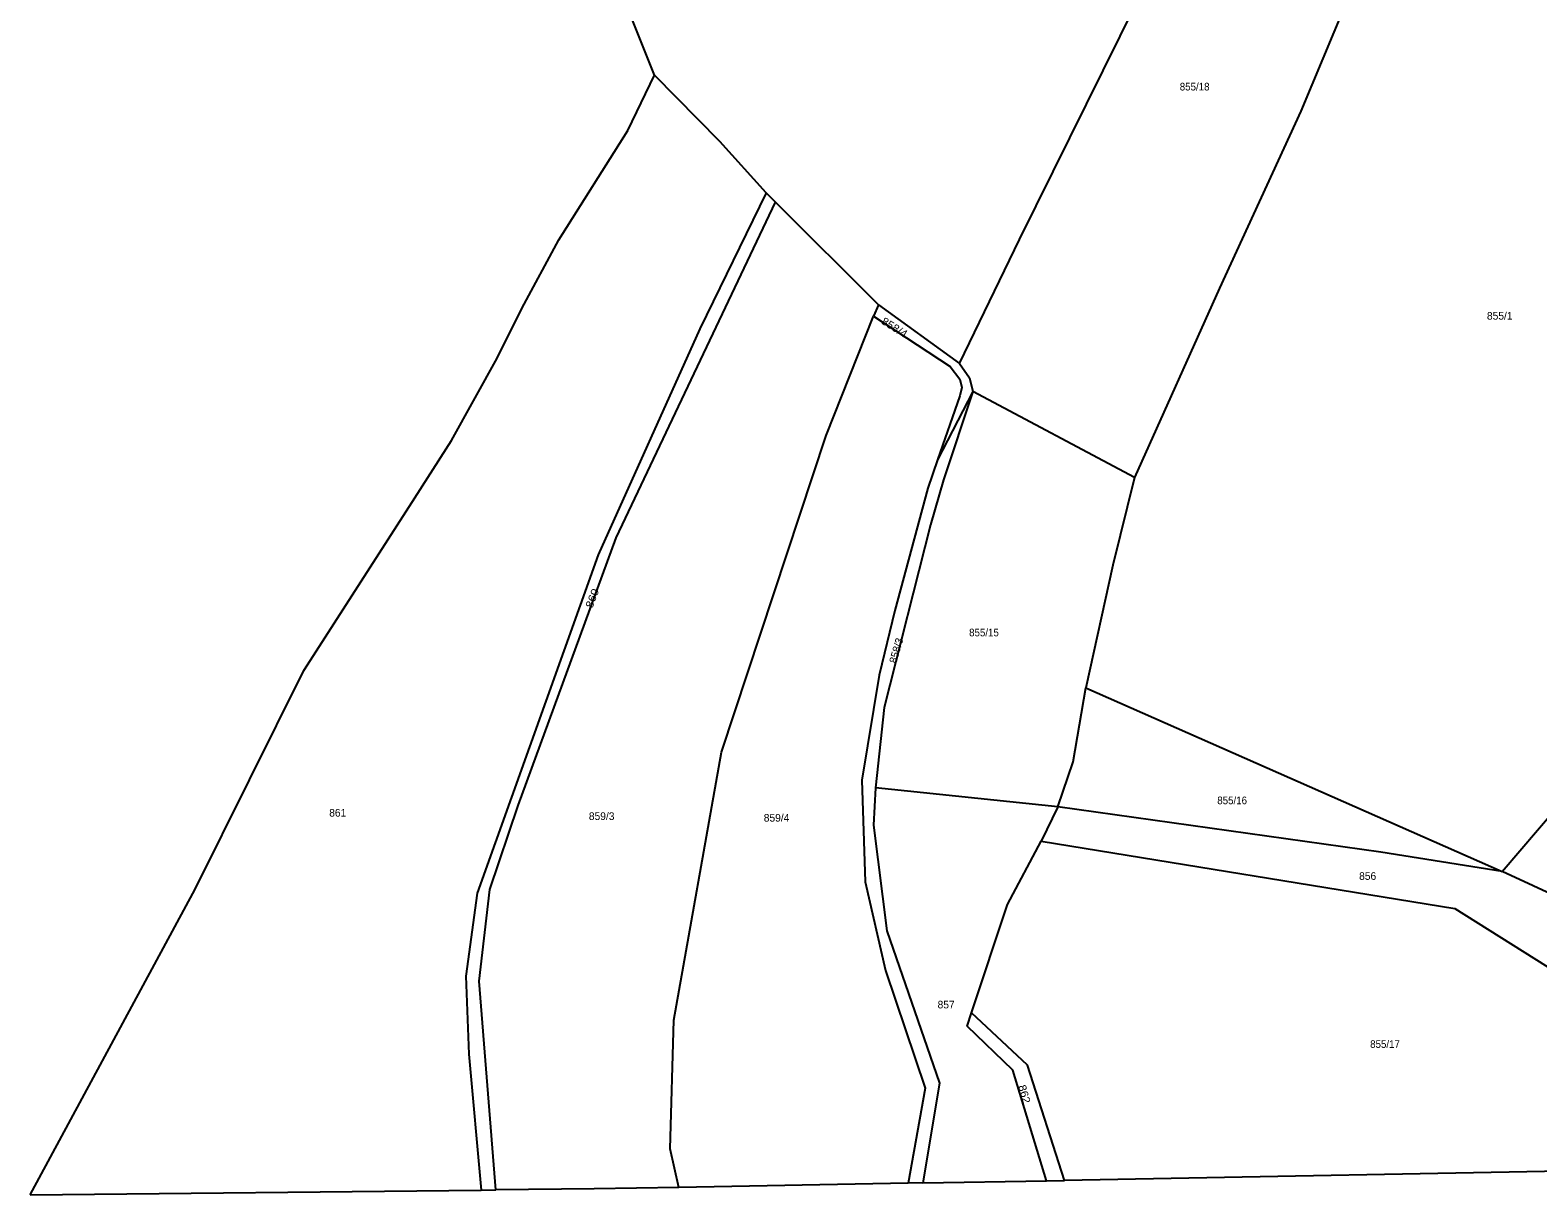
# Model space of a CAD drawing. Extents: x -687135 to -684370, y -1007309 to -1005782.
# Drawn here: x -686161.7 to -685826.9, y -1007308.8 to -1007050.2 of the extents above; entities that cross this region are included whole.
import ezdxf

# ---------------------------------------------------------------- set-up
doc = ezdxf.new("R2010")
doc.units = 0
doc.header["$LTSCALE"] = 0.68
doc.layers.add('1', color=7, linetype='Continuous', lineweight=25)
doc.layers.add('2', color=7, linetype='Continuous')

msp = doc.modelspace()

# ---------------------------------------------------------------- linework, layer by layer
at = {"layer": '1'}
for p, q in [((-685996.12, -1007088.35), (-685973.31, -1007111.15)), ((-685973.31, -1007111.15), (-685974.36, -1007113.66)), ((-685973.31, -1007111.15), (-685955.32, -1007124.17)), ((-685952.34, -1007130.44), (-685960.15, -1007145.6)), ((-685916.46, -1007149.49), (-685952.34, -1007130.44)), ((-685933.44, -1007222.64), (-685973.98, -1007218.44)), ((-685933.44, -1007222.64), (-685937.16, -1007230.29)), ((-685963.46, -1007306.2), (-685935.98, -1007305.71)), ((-685935.98, -1007305.71), (-685931.97, -1007305.63)), ((-686161.67, -1007308.85), (-686061.49, -1007307.79)), ((-686061.49, -1007307.79), (-686058.24, -1007307.76)), ((-685966.67, -1007306.26), (-686017.65, -1007307.19)), ((-685963.46, -1007306.2), (-685966.67, -1007306.26))]:
    msp.add_line(p, q, dxfattribs=at)
for points in [[(-685955.32, -1007124.17), (-685941.96, -1007096.65), (-685915.9, -1007044), (-685895.22, -1006995.76), (-685878.25, -1006963.02)], [(-685846.06, -1006988.01), (-685879.53, -1007068.15), (-685897.56, -1007107.5), (-685916.46, -1007149.49)], [(-686024.97, -1007055.32), (-686029.1, -1007045), (-686042.48, -1007024.33), (-686039.71, -1007008.65)], [(-686028.91, -1007072.46), (-686023.04, -1007060.16), (-686024.97, -1007055.32)], [(-685998.2, -1007086.28), (-686008.55, -1007074.89), (-686023.04, -1007060.16)], [(-686057.97, -1007123.03), (-686052.45, -1007112), (-686044.28, -1007096.71), (-686028.91, -1007072.46)], [(-685998.2, -1007086.28), (-686012.97, -1007116.48), (-686035.54, -1007166.68), (-686062.38, -1007241.82), (-686064.89, -1007260.27), (-686064.24, -1007277.61), (-686061.49, -1007307.79)], [(-686058.24, -1007307.76), (-686061.99, -1007261.37), (-686059.57, -1007241.06), (-686053.3, -1007222.35), (-686031.52, -1007162.93), (-685996.12, -1007088.35), (-685998.2, -1007086.28)], [(-686017.65, -1007307.19), (-686019.52, -1007298.6), (-686018.76, -1007270.05), (-686008.12, -1007210.56), (-685984.9, -1007140.21), (-685974.36, -1007113.66)], [(-685974.36, -1007113.66), (-685957.39, -1007124.85), (-685955.21, -1007127.66), (-685954.74, -1007129.52), (-685955.21, -1007131.39), (-685960.15, -1007145.6)], [(-686077.45, -1007155.91), (-686068.09, -1007141.32), (-686057.97, -1007123.03)], [(-685955.32, -1007124.17), (-685953.1, -1007127.35), (-685952.34, -1007130.44)], [(-685952.34, -1007130.44), (-685958.83, -1007150.06), (-685961.71, -1007160.02), (-685972.02, -1007200.58), (-685973.98, -1007218.44)], [(-685960.15, -1007145.6), (-685962.33, -1007151.87), (-685969.69, -1007179.06), (-685973.11, -1007193.39), (-685977.01, -1007216.74), (-685976.24, -1007239.3), (-685971.71, -1007259.05), (-685962.91, -1007285.14), (-685966.67, -1007306.26)], [(-685916.46, -1007149.49), (-685921.28, -1007169.02), (-685927.24, -1007196.24), (-685834.78, -1007237.06)], [(-686161.67, -1007308.85), (-686125.03, -1007240.98), (-686100.89, -1007192.42), (-686077.45, -1007155.91)], [(-685933.44, -1007222.64), (-685930.03, -1007212.67), (-685927.24, -1007196.24)], [(-685973.98, -1007218.44), (-685974.36, -1007226.74), (-685971.4, -1007250.22), (-685959.73, -1007284.01), (-685963.46, -1007306.2)], [(-685834.78, -1007237.06), (-685823.03, -1007223.25), (-685820.34, -1007219.84)], [(-685834.78, -1007237.06), (-685861.75, -1007232.73), (-685933.44, -1007222.64)], [(-685952.66, -1007268.42), (-685944.64, -1007244.37), (-685937.16, -1007230.29)], [(-685937.16, -1007230.29), (-685845.31, -1007245.22), (-685817.39, -1007262.76), (-685794.79, -1007289.87), (-685803.04, -1007266.06), (-685800.57, -1007257.03), (-685815.07, -1007246.11), (-685834.78, -1007237.06)], [(-685935.98, -1007305.71), (-685943.45, -1007281.18), (-685953.61, -1007271.35), (-685952.66, -1007268.42)], [(-685931.97, -1007305.63), (-685940.2, -1007280.06), (-685952.66, -1007268.42)], [(-685716.84, -1007305.32), (-685721.26, -1007305.36), (-685729.55, -1007305.43), (-685805.63, -1007303.31), (-685931.97, -1007305.63)], [(-686017.65, -1007307.19), (-686036.45, -1007307.53), (-686058.24, -1007307.76)]]:
    msp.add_lwpolyline(points, dxfattribs=at)

# ---------------------------------------------------------------- texts
at = {"layer": '2', "width": 0.95}
for s, p in [('855/18', (-685906.38, -1007063.559)), ('855/15', (-685953.16, -1007184.799)), ('855/16', (-685898.05, -1007222.09)), ('855/17', (-685864.1, -1007276.21))]:
    msp.add_text(s, height=1.7, dxfattribs=at).set_placement(p)
at = {"layer": '2'}
for s, rotation, width, p in [('858/4', 328, 1.1, (-685972.83, -1007115.25)), ('860', 69, 1.15, (-686036.836, -1007178.694)), ('862', 286, 1.1, (-685942.257, -1007284.694))]:
    msp.add_text(s, height=1.7, rotation=rotation, dxfattribs=dict(at, width=width)).set_placement(p)
for s, p in [('855/1', (-685838.17, -1007114.46)), ('861', (-686095.26, -1007224.84)), ('859/3', (-686037.6, -1007225.59)), ('859/4', (-685998.76, -1007225.95)), ('856', (-685866.55, -1007238.89)), ('857', (-685960.16, -1007267.44))]:
    msp.add_text(s, height=1.7, dxfattribs=at).set_placement(p)
msp.add_text('858/3', height=1.7, rotation=74, dxfattribs=at).set_placement((-685969.322, -1007190.924))

doc.saveas('drawing.dxf')
